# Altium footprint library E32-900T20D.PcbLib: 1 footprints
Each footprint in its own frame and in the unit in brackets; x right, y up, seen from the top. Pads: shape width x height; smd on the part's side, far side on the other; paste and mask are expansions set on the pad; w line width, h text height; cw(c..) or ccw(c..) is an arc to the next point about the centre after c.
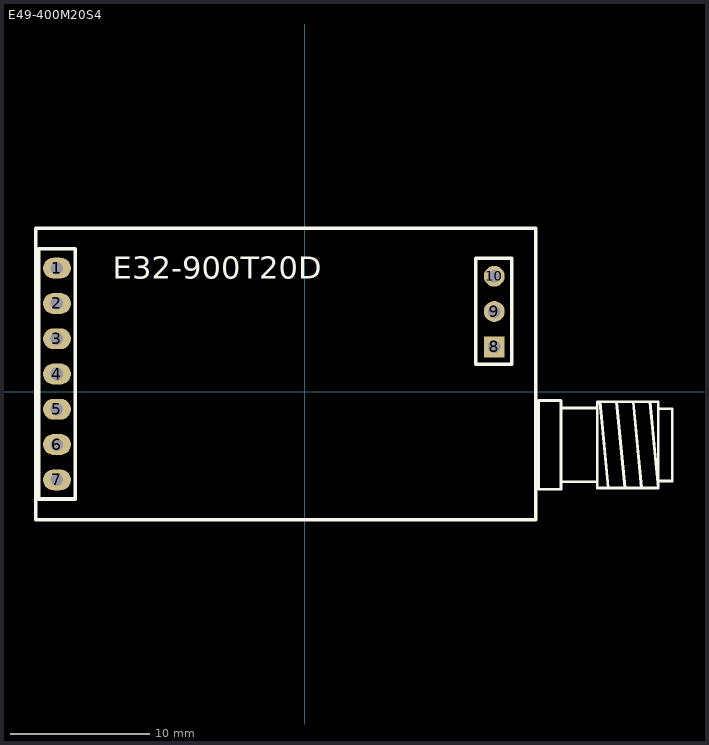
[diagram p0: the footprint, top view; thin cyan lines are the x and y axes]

## E49-400M20S4 [mm]
pads (10):
  oval 2x1.5 hole 0.9: 1(-17.841,8.903) 2(-17.841,6.363) 3(-17.841,3.823) 4(-17.841,1.283) 5(-17.841,-1.257) 6(-17.841,-3.797) 7(-17.841,-6.337)
  rect 1.5x1.5 hole 0.9: 8(13.635,3.238)
  round 1.5 hole 0.9: 9(13.635,5.778) 10(13.635,8.318)
Top Layer:
  lines w0.203: -17.841,-1.257 -17.677,-1.093
  lines w0.5: -18.153,9.393 -17.696,9.393 cw(c-17.696,8.678) -17.191,9.184 ; -17.893,-0.76 -17.86,-0.793 ; -17.841,1.283 -17.32,1.283
Top Overlay:
  lines w0.2: 18.448,-6.467 21.048,-6.467 ; 18.448,-1.167 21.048,-1.167 ; 21.248,-0.717 21.848,-6.917 ; 22.448,-0.717 23.048,-6.917 ; 23.648,-0.717 24.248,-6.917 ; 24.848,-0.717 25.448,-6.917 ; 25.448,-6.417 26.448,-6.417 26.448,-1.217 25.448,-1.217 ; 25.448,-6.917 25.448,-0.717 21.048,-0.717 21.048,-6.917 25.448,-6.917 ; 16.848,-7.017 18.448,-7.017 18.448,-0.617 16.848,-0.617 16.848,-7.017
  lines w0.254: -19.365,-9.217 -19.365,11.783 16.635,11.783 16.635,-9.217 -19.365,-9.217 ; -19.141,-7.717 -16.541,-7.717 -16.541,10.283 -19.141,10.283 -19.141,-7.717 ; 12.3,2 14.9,2 14.9,9.6 12.3,9.6 12.3,2
  text "E32-900T20D" at -13.831,8.151 h1.6
Bottom Overlay:
  lines w0.127: -19.141,10.283 -19.141,-7.717 -16.541,-7.717 -16.541,10.283
  lines w0.2: 12.365,1.968 14.905,1.968 14.905,9.588 12.365,9.588
Keep-Out Layer:
  lines w0.1: -19.365,-9.217 -19.365,11.783 16.635,11.783 16.635,-9.217 -19.365,-9.217
Mechanical 1:
  lines w0.1: -19.365,-9.217 16.635,-9.217 16.635,11.783 -19.365,11.783 -19.365,-9.217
